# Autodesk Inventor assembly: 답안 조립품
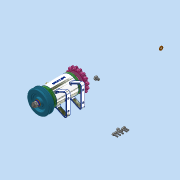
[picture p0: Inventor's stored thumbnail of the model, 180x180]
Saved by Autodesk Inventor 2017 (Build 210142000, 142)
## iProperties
Part Number: 답안 조립품
Material: 일반
Document SubType Name: Assembly
Designer: Administrator
Author: Administrator
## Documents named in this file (16)
- C:\Users\Administrator\Desktop\711206V1031\답안 조립품.iam
- C:\Users\Administrator\Desktop\711206V1031\V벨트풀리.ipt
- C:\Users\Administrator\Desktop\711206V1031\너트 M8.ipt
- C:\Users\Administrator\Desktop\711206V1031\니플 M6 x 0.75.ipt
- C:\Users\Administrator\Desktop\711206V1031\베어링 6002.ipt
- C:\Users\Administrator\Desktop\711206V1031\본체.ipt
- C:\Users\Administrator\Desktop\711206V1031\볼트 M4 x 12.ipt
- C:\Users\Administrator\Desktop\711206V1031\볼트 M6 x 8.ipt
- C:\Users\Administrator\Desktop\711206V1031\스프로킷.ipt
- C:\Users\Administrator\Desktop\711206V1031\스프링와셔 8.ipt
- C:\Users\Administrator\Desktop\711206V1031\오일 실 15 x 25 x 7.ipt
- C:\Users\Administrator\Desktop\711206V1031\와셔 6 x 11.5.ipt
- C:\Users\Administrator\Desktop\711206V1031\와셔 8 x 17.ipt
- C:\Users\Administrator\Desktop\711206V1031\축.ipt
- C:\Users\Administrator\Desktop\711206V1031\커버.ipt
- C:\Users\Administrator\Desktop\711206V1031\키 3 x 3.ipt
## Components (17 placed, 3 different names)
1. V벨트풀리:1
2. KS B 2023 6002 - 15 x 32 x 9:1
3. KS B 2023 6002 - 15 x 32 x 9:2
4. ISO 4762 M4 x 12:2
5. ISO 4762 M4 x 12:3
6. ISO 4762 M4 x 12:4
7. ISO 4762 M4 x 12:5
8. ISO 4762 M4 x 12:6
9. ISO 4762 M4 x 12:7
10. ISO 4762 M4 x 12:1
11. ISO 4762 M4 x 12:9
12. ISO 4762 M4 x 12:10
13. ISO 4762 M4 x 12:11
14. ISO 4762 M4 x 12:8
15. ISO 4762 M4 x 12:12
16. ISO 4762 M4 x 12:13
17. ISO 4762 M4 x 12:14
